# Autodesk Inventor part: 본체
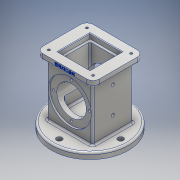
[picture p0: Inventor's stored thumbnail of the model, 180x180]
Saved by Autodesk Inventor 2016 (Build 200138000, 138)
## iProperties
Created: 2018-10
Part Number: 본체
Material: 알루미늄 6061
Document SubType Name: Modeling
Designer: 3sil_cad019
Density: 2.7 g/cm^3
Appearance: 알루미늄 - 평지
Mass: 983.145 g
Surface Area: 746.27 cm^2
Volume: 364.128 cm^3
Author: 3sil_cad019
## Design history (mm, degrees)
sketch "스케치1"
  geometry: L1 (-37, 33)-(37, 33); L2 (37, 33)-(37, -33); L3 (37, -33)-(-37, -33); L4 (-37, -33)-(-37, 33); 3 further points
  constraints: 8 end point, 2 midpoint, 2 parallel, 1 horizontal, 1 horizontal alignment, 1 perpendicular, 1 vertical alignment
  dimensions: "d0" = 74 distance of L1.start L1.end; "d1" = 66 distance of L3.end L1.start
extrude "돌출1" new body sketch "스케치1" distance "d2" = 108; taper "d3" = 0 deg
sketch "스케치2"
  geometry: L1 (74, 0)-(0, 0) reference; C1 r 24 at (37, 54); 2 further points
  constraints: 1 centre point, 1 midpoint, 1 vertical alignment
  dimensions: "d4" = 48 diameter of C1; "d5" = 54 distance from line of C1.centre L1
extrude "돌출2" cut sketch "스케치2" stored distance "d6" = 108; taper "d7" = 0 deg
sketch "스케치3"
  geometry: C1 r 24 at (37, 54) reference; C2 r 35 at (37, 54); 1 further point
  constraints: 1 centre point, 1 coincident
  dimensions: "d8" = 70 diameter of C2
extrude "돌출3" cut sketch "스케치3" distance "d9" = 3; taper "d10" = 0 deg
sketch "스케치4"
  geometry: C1 r 62.5 at (0, 0); 1 further point
  constraints: 1 centre point, 1 coincident
  dimensions: "d11" = 125 diameter of C1
extrude "돌출4" join sketch "스케치4" distance "d12" = 10; taper "d13" = 0 deg
sketch "스케치5"
  geometry: L1 (-46, 41)-(46, 41); L2 (46, 41)-(46, -41); L3 (46, -41)-(-46, -41); L4 (-46, -41)-(-46, 41); 3 further points
  constraints: 8 end point, 2 midpoint, 2 parallel, 1 horizontal, 1 horizontal alignment, 1 perpendicular, 1 vertical alignment
  dimensions: "d14" = 92 distance of L1.start L1.end; "d15" = 82 distance of L1.end L2.end
extrude "돌출5" join sketch "스케치5" distance "d16" = 10; taper "d17" = 0 deg
sketch "스케치6"
  geometry: L1 (-22, 22)-(22, 22); L2 (22, 22)-(22, -22); L3 (22, -22)-(-22, -22); L4 (-22, -22)-(-22, 22); 3 further points
  constraints: 8 end point, 2 midpoint, 2 parallel, 1 horizontal, 1 horizontal alignment, 1 perpendicular, 1 vertical alignment
  dimensions: "d18" = 44 distance of L1.start L1.end; "d19" = 44 distance of L3.end L1.start
extrude "돌출6" cut sketch "스케치6" distance "d20" = 82; taper "d21" = 0 deg
sketch "스케치7"
  geometry: L1 (-26, 26)-(26, 26); L2 (26, 26)-(26, -26); L3 (26, -26)-(-26, -26); L4 (-26, -26)-(-26, 26); 3 further points
  constraints: 8 end point, 2 midpoint, 2 parallel, 1 horizontal, 1 horizontal alignment, 1 perpendicular, 1 vertical alignment
  dimensions: "d22" = 52 distance of L1.start L1.end; "d24" = 52 distance of L1.end L2.end
extrude "돌출7" cut sketch "스케치7" distance "d25" = 8; taper "d26" = 0 deg
sketch "스케치8"
  geometry: C1 r 28 at (0, 0); 1 further point
  constraints: 1 centre point, 1 coincident
  dimensions: "d27" = 56 diameter of C1
extrude "돌출8" cut sketch "스케치8" distance "d28" = 18; taper "d29" = -10 deg
sketch "스케치9"
  geometry: C1 r 24 at (0, 0) reference; 2 further points
  constraints: 1 vertical alignment
  dimensions: "d30" = 29 distance of C1.centre point (0, 29)
hole "구멍1" sketch "스케치9" at (0, 29) diameter "d31" = 4; stored, may be unused: countersink angle "d35" = 90 deg, drill point angle "d37" = 118 deg; dims "d32" = 6, "d33" = 4, "d34" = 2, "d36" = 6
fillet "모깎기1" dims "d44" = 10
sketch "스케치11"
  geometry: L1 (-46, -31)-(-46, 31) reference; L2 (36, -41)-(-36, -41) reference; L3 (46, 31)-(46, -31) reference; L4 (-36, 41)-(36, 41) reference; L5 (-26, -26)-(-26, 26) reference; L6 (-26, 26)-(26, 26) reference; L7 (26, 26)-(26, -26) reference; L8 (26, -26)-(-26, -26) reference; A1 r 10 centre (-36, 31) between (-36, 41) and (-46, 31) reference; A2 r 10 centre (-36, -31) between (-46, -31) and (-36, -41) reference; A3 r 10 centre (36, -31) between (36, -41) and (46, -31) reference; A4 r 10 centre (36, 31) between (46, 31) and (36, 41) reference; 1 further point
hole "구멍2" sketch "스케치11" at (-36, -31), (-36, 31), (36, 31), (36, -31) diameter "d45" = 4; stored, may be unused: countersink angle "d49" = 90 deg, drill point angle "d51" = 118 deg; dims "d46" = 6, "d47" = 4, "d48" = 2, "d50" = 6
sketch "스케치12" dims "d52" = 100
  geometry: C1 r 62.5 at (0, 0) reference; 3 further points
  constraints: 2 vertical alignment, 1 coincident, 2 other
hole "구멍3" sketch "스케치12" at (0, 50) diameter "d53" = 9; stored, may be unused: countersink angle "d57" = 90 deg, drill point angle "d59" = 118 deg; dims "d54" = 6, "d55" = 4, "d56" = 2, "d58" = 6
sketch "스케치13"
  geometry: L1 (-10, 0)-(-10, -10) reference; L2 (72, 0)-(0, 0) reference; 2 further points
  constraints: 1 other
  dimensions: "d63" = 46 distance from line of point (36, -4) L1; "d64" = 4 distance from line of point (36, -4) L2
feature "엠보싱1" sketch "스케치13" dims "d0" = 74, "d1" = 66, "d65" = 0.5, "d66" = 0
sketch "스케치15"
  geometry: L1 (-98, 64)-(-98, 2) reference; L2 (10, 95.5)-(10, -29.5) reference; 4 further points
  constraints: 2 horizontal alignment, 1 midpoint
  dimensions: "d69" = 37 distance from line of point (-27, 33) L2; "d70" = 43 distance of point (-27, 33) point (-70, 33)
hole "구멍4" sketch "스케치15" at (-70, 33), (-27, 33) diameter "d71" = 5; stored, may be unused: countersink angle "d75" = 90 deg, drill point angle "d77" = 118 deg; dims "d72" = 6, "d73" = 4, "d74" = 2, "d76" = 17.75
fillet "모깎기2" dims "d78" = 3
fillet "모깎기3" dims "d79" = 3
fillet "모깎기4" dims "d80" = 3
fillet "모깎기5" dims "d81" = 3
chamfer "모따기1" distance "d82" = 1; stored, may be unused: second distance "d83" = 2, angle "d84" = 45 deg
node "솔리드1"
mirror "대칭1"
pattern_circular "원형 패턴1" dims angle "d39" = 360 deg
mirror "대칭2"
pattern_circular "원형 패턴2" dims angle "d61" = 360 deg
node "투영된 루프1"
